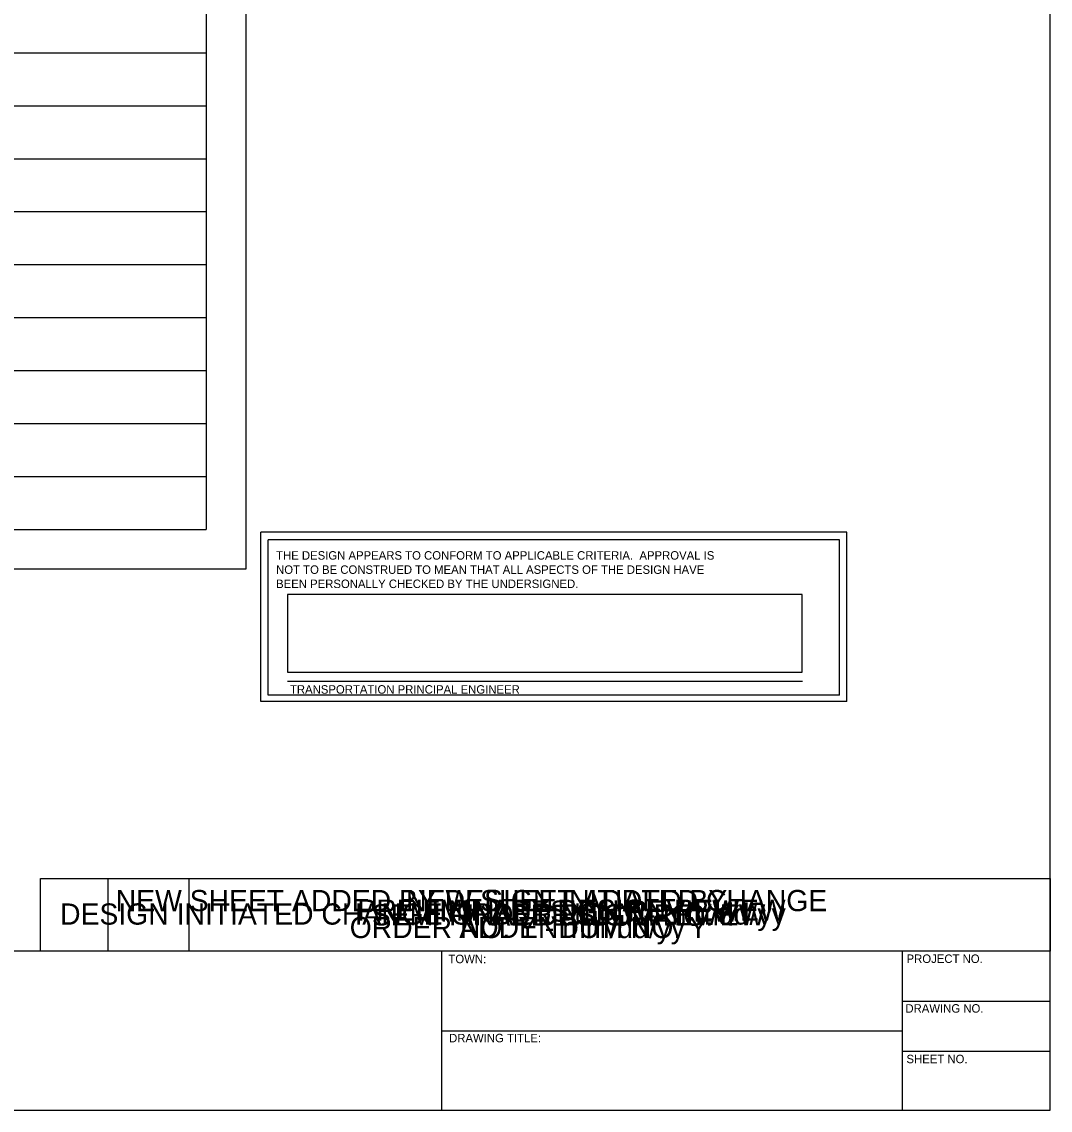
# Model space of a CAD drawing. Extents: x 0 to 31.8, y -0.5 to 20.8.
# Drawn here: x 22.04 to 31.75, y 0 to 10.27 of the extents above; entities that cross this region are included whole.
import ezdxf

# ---------------------------------------------------------------- set-up
doc = ezdxf.new("R2010")
doc.units = 0
for name, color, linetype in [('CT_Approval_Block', 7, 'Continuous'), ('CT_Approval_Block_Written_Signatures', 7, 'Continuous'), ('CT_Border_Perimeter_Shape', 7, 'Continuous'), ('CT_DigSig_Field1', 7, 'Continuous'), ('CT_Note_Addendum', 7, 'Continuous'), ('CT_Note_Design_Initiated_Change_Order', 7, 'Continuous'), ('CT_Note_Final_Design_Review', 7, 'Continuous'), ('CT_Note_New_Sheet_by_Addendum', 7, 'Continuous'), ('CT_Note_New_Sheet_by_Design_Initiated_Change_Order', 7, 'Continuous'), ('CT_Note_Preliminary_Design_Review', 7, 'Continuous'), ('CT_Note_Semi_Final_Design_Review', 7, 'Continuous'), ('CT_Title_Block_Linework', 7, 'Continuous'), ('CT_Title_Block_Text', 7, 'Continuous'), ('CT_TSH_Line_Work_Major', 7, 'Continuous'), ('CT_TSH_Line_Work_Minor', 7, 'Continuous')]:
    doc.layers.add(name, color=color, linetype=linetype)

msp = doc.modelspace()

# ---------------------------------------------------------------- linework, layer by layer
at = {"layer": 'CT_Approval_Block'}
for p, q in [((29.831, 5.455), (24.297, 5.455)), ((24.297, 3.859), (24.297, 5.455)), ((29.831, 3.859), (29.831, 5.455)), ((24.367, 3.917), (24.367, 5.384)), ((29.761, 5.384), (24.367, 5.384)), ((29.761, 3.917), (29.761, 5.384)), ((29.761, 3.917), (24.367, 3.917)), ((29.831, 3.859), (24.297, 3.859))]:
    msp.add_line(p, q, dxfattribs=at)
at = {"layer": 'CT_Approval_Block_Written_Signatures'}
msp.add_line((24.551, 4.049), (29.412, 4.049), dxfattribs=at)
at = {"layer": 'CT_Border_Perimeter_Shape'}
msp.add_lwpolyline([(0, 0), (31.75, 0), (31.75, 20.75), (0, 20.75)], close=True, dxfattribs=at)
at = {"layer": 'CT_DigSig_Field1'}
msp.add_lwpolyline([(24.551, 4.135), (29.407, 4.135), (29.407, 4.867), (24.551, 4.867)], close=True, dxfattribs=at)
at = {"layer": 'CT_Note_Addendum'}
msp.add_lwpolyline([(23.621, 2.186), (31.75, 2.186), (31.75, 1.5), (23.621, 1.5)], close=True, dxfattribs=at)
msp.add_lwpolyline([(23.621, 2.186), (31.75, 2.186), (31.75, 1.5), (23.621, 1.5)], close=True, dxfattribs=at)
at = {"layer": 'CT_Note_Design_Initiated_Change_Order'}
msp.add_lwpolyline([(22.217, 2.186), (31.75, 2.186), (31.75, 1.5), (22.217, 1.5)], close=True, dxfattribs=at)
msp.add_lwpolyline([(22.217, 2.186), (31.75, 2.186), (31.75, 1.5), (22.217, 1.5)], close=True, dxfattribs=at)
at = {"layer": 'CT_Note_Final_Design_Review'}
msp.add_lwpolyline([(23.621, 2.186), (31.75, 2.186), (31.75, 1.5), (23.621, 1.5)], close=True, dxfattribs=at)
at = {"layer": 'CT_Note_New_Sheet_by_Addendum'}
msp.add_lwpolyline([(23.621, 2.186), (31.75, 2.186), (31.75, 1.5), (23.621, 1.5)], close=True, dxfattribs=at)
msp.add_lwpolyline([(23.621, 2.186), (31.75, 2.186), (31.75, 1.5), (23.621, 1.5)], close=True, dxfattribs=at)
at = {"layer": 'CT_Note_New_Sheet_by_Design_Initiated_Change_Order'}
msp.add_lwpolyline([(22.858, 2.186), (31.75, 2.186), (31.75, 1.5), (22.858, 1.5)], close=True, dxfattribs=at)
msp.add_lwpolyline([(22.858, 2.186), (31.75, 2.186), (31.75, 1.5), (22.858, 1.5)], close=True, dxfattribs=at)
at = {"layer": 'CT_Note_Preliminary_Design_Review'}
msp.add_lwpolyline([(23.621, 2.186), (31.75, 2.186), (31.75, 1.5), (23.621, 1.5)], close=True, dxfattribs=at)
at = {"layer": 'CT_Note_Semi_Final_Design_Review'}
msp.add_lwpolyline([(23.621, 2.186), (31.75, 2.186), (31.75, 1.5), (23.621, 1.5)], close=True, dxfattribs=at)
msp.add_lwpolyline([(23.621, 2.186), (31.75, 2.186), (31.75, 1.5), (23.621, 1.5)], close=True, dxfattribs=at)
at = {"layer": 'CT_Title_Block_Linework'}
for p, q in [((31.75, 1.5), (0, 1.5)), ((26.004, 1.5), (26.004, 0)), ((30.351, 1.5), (30.351, 0)), ((30.351, 1.031), (31.75, 1.031)), ((26.004, 0.75), (30.351, 0.75)), ((30.351, 0.556), (31.75, 0.556))]:
    msp.add_line(p, q, dxfattribs=at)
at = {"layer": 'CT_TSH_Line_Work_Major'}
for p, q in [((24.156, 16.357), (24.156, 5.107)), ((24.156, 5.107), (4.156, 5.107))]:
    msp.add_line(p, q, dxfattribs=at)
at = {"layer": 'CT_TSH_Line_Work_Minor'}
for p, q in [((23.781, 15.982), (23.781, 5.482)), ((14.156, 9.982), (23.781, 9.982)), ((14.156, 9.482), (23.781, 9.482)), ((14.156, 8.982), (23.781, 8.982)), ((14.156, 8.482), (23.781, 8.482)), ((14.156, 7.982), (23.781, 7.982)), ((14.156, 7.482), (23.781, 7.482)), ((14.156, 6.982), (23.781, 6.982)), ((14.156, 6.482), (23.781, 6.482)), ((14.156, 5.982), (23.781, 5.982)), ((14.156, 5.482), (23.781, 5.482))]:
    msp.add_line(p, q, dxfattribs=at)

# ---------------------------------------------------------------- texts
at = {"layer": 'CT_Approval_Block'}
for s, p in [('THE DESIGN APPEARS TO CONFORM TO APPLICABLE CRITERIA.  APPROVAL IS', (24.442, 5.197)), ('NOT TO BE CONSTRUED TO MEAN THAT ALL ASPECTS OF THE DESIGN HAVE ', (24.442, 5.063)), ('BEEN PERSONALLY CHECKED BY THE UNDERSIGNED.', (24.442, 4.929))]:
    msp.add_text(s, height=0.08, dxfattribs=at).set_placement(p)
at = {"layer": 'CT_Approval_Block_Written_Signatures'}
msp.add_text('TRANSPORTATION PRINCIPAL ENGINEER', height=0.08, dxfattribs=at).set_placement((24.573, 3.932))
at = {"layer": 'CT_Note_Addendum'}
msp.add_text('ADDENDUM NO. Y', height=0.2, dxfattribs=at).set_placement((26.475, 1.741))
at = {"layer": 'CT_Note_Design_Initiated_Change_Order'}
msp.add_text('DESIGN INITIATED CHANGE ORDER NO. Y - mm/dd/yy', height=0.2, dxfattribs=at).set_placement((22.403, 1.752))
at = {"layer": 'CT_Note_Final_Design_Review'}
msp.add_text('FINAL DESIGN REVIEW', height=0.2, dxfattribs=at).set_placement((25.825, 1.78))
at = {"layer": 'CT_Note_New_Sheet_by_Addendum'}
for s, p in [('NEW SHEET ADDED BY', (25.67, 1.879)), ('ADDENDUM NO. Y', (26.171, 1.625))]:
    msp.add_text(s, height=0.2, dxfattribs=at).set_placement(p)
at = {"layer": 'CT_Note_New_Sheet_by_Design_Initiated_Change_Order'}
for s, p in [('NEW SHEET ADDED BY DESIGN INITIATED CHANGE', (22.928, 1.879)), ('ORDER NO. Y - mm/dd/yy', (25.137, 1.625))]:
    msp.add_text(s, height=0.2, dxfattribs=at).set_placement(p)
at = {"layer": 'CT_Note_Preliminary_Design_Review'}
msp.add_text('PRELIMINARY DESIGN REVIEW', height=0.2, rotation=360, dxfattribs=at).set_placement((25.21, 1.789))
at = {"layer": 'CT_Note_Semi_Final_Design_Review'}
msp.add_text('SEMI FINAL DESIGN REVIEW', height=0.2, dxfattribs=at).set_placement((25.346, 1.744))
at = {"layer": 'CT_Title_Block_Text'}
for s, p in [('TOWN:', (26.069, 1.388)), ('PROJECT NO.', (30.394, 1.39)), ('DRAWING NO.', (30.383, 0.921)), ('DRAWING TITLE:', (26.075, 0.641)), ('SHEET NO.', (30.393, 0.444))]:
    msp.add_text(s, height=0.08, rotation=360, dxfattribs=at).set_placement(p)

doc.saveas('drawing.dxf')
